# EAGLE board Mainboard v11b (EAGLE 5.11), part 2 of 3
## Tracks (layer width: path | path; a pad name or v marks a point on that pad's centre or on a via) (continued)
KICK_ERR  (via drill 0.3) (continued)
  Bottom 0.203: v30.46,59.39 30.46,61.3 28.55,63.2 19.98,63.2 18.08,65.11 18.08,67.65 v14.58,71.14
KICK_NSS  (via drill 0.3)
  Top 0.203: v29.19,58.76 34.9,58.76 35.86,57.81 36.17,57.49 40.46,57.49 40.72,57.75 IC15.11 | Q2.1 25.06,63.38 v25.06,61.3 | E1.1 13.59,64.83 14.27,64.16 v16.17,64.16
  Bottom 0.203: v29.19,58.76 25.7,58.76 25.06,59.39 v25.06,61.3 19.03,61.3 v16.17,64.16
KILL  (via drill 0.3)
  Top 0.203: IC3.2 100.62,107.66 100.31,107.97 | 100.31,107.97 100.31,109.24 100.62,109.56 R10.1 | 99.67,107.97 100.31,107.97 | v60.78,68.44 61.41,68.44 66.81,68.44 v68.88,70.51 | IC15.27 43.03,49.75 45.38,52.09 v45.38,53.05 | 99.67,107.97 99.67,108.19 R13.1 | v99.04,106.38 99.67,107.02 99.67,107.97
  Bottom 0.203: v99.04,106.38 98.88,106.23 95.39,106.23 93.8,104.64 75.7,104.64 73.48,102.42 73.48,92.73 69.99,89.24 69.99,85.11 63.95,79.08 63.95,76.22 68.88,71.3 v68.88,70.51 | v60.78,68.44 59.67,68.44 59.51,68.28 59.51,66.7 56.49,63.68 56.49,60.66 50.62,54.79 49.98,54.79 48.55,53.36 47.92,53.36 47.6,53.05 v45.38,53.05
LCD_ON
  Top 0.203: IC15.87 65.7,52.25 67.92,50.03 67.92,46.7 69.86,44.75 E14.2
LCD_RESET
  Top 0.203: IC15.88 63.01,52.73 66.02,52.73 68.4,50.35 68.4,46.85 70.26,44.99 E14.4
LED1  (via drill 0.3)
  Top 0.203: IC15.13 42.57,56.75 43,57.17 v43,57.81 | v27.6,118.13 27.6,118.94 Q8.1
  Bottom 0.203: v43,57.81 43.95,57.81 44.27,58.12 45.06,58.92 45.06,60.51 42.84,62.73 42.84,68.28 44.43,69.87 44.43,76.86 43.48,77.81 43.48,91.46 38.87,96.07 38.87,100.83 36.81,102.89 36.81,111.78 35.38,113.21 32.52,113.21 v27.6,118.13
LED2  (via drill 0.3)
  Top 0.203: IC15.9 42.85,58.75 v43,58.6 | v18.39,123.53 18.39,124 Q9.1
  Bottom 0.203: v43,58.6 44.11,58.6 44.59,59.08 44.59,60.35 42.36,62.57 42.36,68.44 43.95,70.03 43.95,76.7 43,77.65 43,91.3 38.39,95.91 38.39,100.67 36.33,102.73 36.33,111.62 35.22,112.73 32.36,112.73 28.23,116.86 22.84,116.86 18.39,121.31 v18.39,123.53
LED3  (via drill 0.3)
  Top 0.203: IC15.132 49.62,65.48 49.19,65.9 48.55,65.9 48.08,66.38 48.08,67.97 48.4,68.28 v50.46,68.28 | v58.4,72.41 58.56,72.25 59.51,72.25 61.89,74.64 61.89,75.11 62.37,75.59 62.37,80.67 64.59,82.89 64.59,84.64 v66.34,86.38 | v78.4,115.91 78.4,116.38 Q11.1
  Bottom 0.203: v78.4,115.91 78.4,107.66 76.34,105.59 75.38,105.59 72.53,102.73 72.53,93.05 66.49,87.02 66.34,86.86 v66.34,86.38 | v50.46,68.28 52.68,68.28 56.81,72.41 v58.4,72.41
LED4  (via drill 0.3)
  Top 0.203: v53,54.63 53,49.87 | IC15.55 52.62,44.41 53,44.79 53,49.87 | 53,49.87 | v88.56,120.35 89.34,120.35 Q10.1 | v66.65,84.8 65.54,83.68 65.54,82.57 63.32,80.35 63.32,75.27 62.84,74.79 v62.84,72.41
  Bottom 0.203: v53,54.63 53.32,54.95 55.86,54.95 59.51,58.6 59.51,63.52 61.26,65.27 61.73,65.75 62.52,66.54 62.84,66.86 v62.84,72.41 | v88.56,120.35 87.29,120.35 79.03,112.1 79.03,107.66 76.5,105.11 75.54,105.11 73,102.58 73,92.89 66.97,86.86 66.97,85.11 v66.65,84.8
M1-BIN+
  Top 0.203: R1.2 91.32,110.56 Q1.5 | IC2.1 90.82,108.65
  Top 0.305: R1.2 91.27,109.09 90.82,108.65
  pour Top (no thermals): 90.78,109.88 90.15,110.51 90.15,116.55 92.37,116.55 92.37,110.51 91.73,109.88
M1-COM  (via drill 0.3)
  Top 0.203: IC17.22 73.48,75.42 73.8,75.11 78.24,75.11 82.36,79.23 R38.2 | IC17.38 73.98,86.57 74.27,86.86 v76.65,86.86 | IC16.3 79.99,88.29 v79.67,87.97
  Bottom 0.203: v76.65,86.86 77.77,87.97 v79.67,87.97
  pour Top (no thermals): 80.62,94.32 83.48,94.32 83.8,94 83.8,79.4 83.48,79.08 82.53,79.08 82.21,79.4 82.21,79.72 82.53,80.03 82.53,81.94 82.21,82.25 80.62,82.25 80.31,82.57 80.62,82.89 82.21,82.89 82.53,83.21 82.53,87.65 82.21,87.97 80.62,87.97 80.31,88.29 80.62,88.61 82.21,88.61 82.53,88.92 82.53,93.37 82.21,93.69 80.62,93.69 80.31,94
M1-HO1
  Top 0.203: IC17.32 77.09,82.05 78.24,83.21 78.24,87.34 80.46,89.56 IC16.2
M1-HO2  (via drill 0.3)
  Top 0.203: IC17.29 77.72,80.55 v77.77,80.51 | IC18.2 80.46,95.27 79.51,94.32 79.51,93.84 v79.03,93.37
  Bottom 0.203: v77.77,80.51 74.75,83.53 74.75,86.54 78.4,90.19 78.4,92.73 v79.03,93.37
M1-HO3
  Top 0.203: IC17.26 77,79.05 77.45,78.6 78.24,78.6 79.03,79.4 79.03,80.83 79.67,81.46 79.67,83.05 80.46,83.84 IC19.2
M1-HO4  (via drill 0.3)
  Top 0.203: IC21.29 29.87,88.09 v29.82,88.13 | IC22.2 27.28,77.81 28.23,78.76 | 28.23,78.76 | 28.23,78.76 28.71,79.24 30.3,79.24 v30.77,79.72
  Bottom 0.203: v29.82,88.13 | v29.82,88.13 32.05,85.91 32.05,83.37 30.77,82.1 v30.77,79.72
M1-HO5
  Top 0.203: IC23.2 27.28,89.24 28.08,90.03 30.14,90.03 30.62,89.56 31.53,89.56 IC21.26
M1-HO6
  Top 0.203: IC20.2 27.28,83.53 27.92,84.16 28.55,84.16 29.35,84.95 29.35,85.43 30.5,86.59 IC21.32
M1-HO7  (via drill 0.3)
  Top 0.203: v29.35,34.95 30.3,34.95 30.5,34.74 IC25.29 | v24.74,26.69 IC26.2
  Bottom 0.203: v29.35,34.95 30.46,34.95 31.41,33.99 31.41,28.6 29.5,26.69 v24.74,26.69
M1-HO8
  Top 0.203: IC25.26 30.91,36.24 30.3,36.85 29.98,36.85 28.71,38.12 IC27.2
M1-HO9  (via drill 0.3)
  Top 0.203: v28.87,33.04 29.07,33.24 IC25.32 | v27.6,32.41 IC24.2
  Bottom 0.203: v28.87,33.04 28.23,33.04 v27.6,32.41
M1-HO10  (via drill 0.3)
  Top 0.203: IC29.29 75.02,29.12 75.07,29.07 v76.5,29.07 | v81.26,38.76 IC30.2
  Bottom 0.203: v76.5,29.07 76.65,29.07 77.13,29.55 77.13,30.19 75.07,32.25 75.07,33.2 80.62,38.76 v81.26,38.76
M1-HO11
  Top 0.203: IC29.26 75.41,27.62 76.18,26.85 78.56,26.85 79.03,27.33 IC31.2
M1-HO12
  Top 0.203: IC29.32 75.5,30.62 77.77,32.88 79.61,32.88 IC28.2
M1-HO13
  Top 0.203: IC34.2 20.35,111.31 24.27,111.31 26.49,109.08 26.49,107.18 26.13,106.82 IC33.29
M1-HO14  (via drill 0.3)
  Top 0.203: IC33.26 24.24,108.32 v23.79,108.77 | v21.57,99.72 IC35.2
  Bottom 0.203: v23.79,108.77 26.65,105.91 26.65,101.94 26.01,101.31 | 26.01,101.31 | 26.01,101.31 24.43,99.72 v21.57,99.72
M1-HO15
  Top 0.203: IC32.2 20.35,105.59 22.84,105.59 23.11,105.32 IC33.32
M1-LO1  (via drill 0.3)
  Top 0.203: IC17.36 76.5,84.05 v76.5,84.8 | v79.03,87.02 IC16.4
  Bottom 0.203: v76.5,84.8 78.72,87.02 v79.03,87.02
M1-LO2
  Top 0.203: IC17.35 77,83.55 77.29,83.84 77.29,88.76 78.08,89.56 78.08,92.1 78.72,92.73 IC18.4
M1-LO3
  Top 0.203: IC17.34 75.07,83.05 74.75,82.73 74.75,78.29 75.38,77.65 79.19,77.65 79.67,78.13 79.67,80.83 80.15,81.3 IC19.4
M1-LO4
  Top 0.203: IC21.35 30.59,85.09 30.3,84.8 30.3,81.46 29.19,80.35 IC22.4
M1-LO5  (via drill 0.3)
  Top 0.203: IC21.34 32.52,85.59 32.84,85.27 32.84,84.32 32.36,83.84 v32.36,82.25 | v28.23,91.78 IC23.4
  Bottom 0.203: v32.36,82.25 33,82.89 33,89.24 30.46,91.78 v28.23,91.78
M1-LO6  (via drill 0.3)
  Top 0.203: IC21.36 30.93,84.59 v30.93,83.84 | IC20.4 27.28,86.06 28.23,85.11 v28.23,84.8
  Bottom 0.203: v30.93,83.84 29.98,84.8 v28.23,84.8
M1-LO7
  Top 0.203: IC26.4 26.96,29.23 27.44,28.76 29.03,28.76 30.46,30.19 32.36,30.19 33.16,30.98 33.16,31.45 32.87,31.74 IC25.35
M1-LO8  (via drill 0.3)
  Top 0.203: v30.14,31.77 30.46,31.77 30.93,32.24 IC25.34 | v30.77,38.12 28.23,40.66 IC27.4
  Bottom 0.203: v30.14,31.77 30.14,33.36 28.71,34.79 28.71,35.11 30.77,37.17 v30.77,38.12
M1-LO9  (via drill 0.3)
  Top 0.203: v30.14,30.82 30.57,31.24 IC25.36 | IC24.4 26.96,34.95 27.6,34.31 v28.23,34.31
  Bottom 0.203: v28.23,34.31 28.55,34.31 29.5,33.36 29.5,31.45 v30.14,30.82
M1-LO10
  Top 0.203: IC29.35 75.73,32.12 76.34,32.73 76.34,35.74 76.97,36.38 79.61,36.38 IC30.4
M1-LO11  (via drill 0.3)
  Top 0.203: IC29.34 73.47,31.62 73.16,31.93 73.16,32.88 73.8,33.52 v73.8,34.15 | v77.13,24.79 IC31.4
  Bottom 0.203: v73.8,34.15 73.64,33.99 73.64,28.28 76.81,24.79 v77.13,24.79
M1-LO12  (via drill 0.3)
  Top 0.203: 79.83,30.6 IC28.4 79.03,30.5 78.72,30.82 v78.4,30.82 | IC29.36 75.28,32.62 v75.7,33.04
  Bottom 0.203: v78.4,30.82 77.92,30.82 v75.7,33.04
M1-LO13  (via drill 0.3)
  Top 0.203: IC33.35 26.2,103.82 26.49,103.53 26.49,103.05 26.01,102.58 v25.54,102.58 | v21.57,113.69 IC34.4
  Bottom 0.203: v25.54,102.58 24.58,103.53 24.58,106.38 22.2,108.77 22.2,113.05 v21.57,113.69
M1-LO14
  Top 0.203: IC33.34 24.1,104.32 23.63,103.84 23.63,102.73 23,102.1 20.35,102.1 IC35.4
M1-LO15  (via drill 0.3)
  Top 0.203: IC33.36 24.74,103.32 v24.74,102.58 | v21.89,106.7 21.89,107.02 20.93,107.97 IC32.4
  Bottom 0.203: v24.74,102.58 24.11,103.21 24.11,106.23 23.63,106.7 v21.89,106.7
M1-VB1
  Top 0.203: IC17.33 76.95,82.55 77.77,83.37 77.77,88.39 C61.1
M1-VB2  (via drill 0.3)
  Top 0.203: IC17.30 77.52,81.05 v77.77,81.3 | v78.72,94.32 78.72,95.06 C62.1
  Bottom 0.203: v77.77,81.3 75.22,83.84 75.22,86.38 79.03,90.19 79.03,92.41 79.67,93.05 79.67,93.69 79.03,94.32 v78.72,94.32
M1-VB3
  Top 0.203: IC17.27 77.13,79.55 77.61,79.08 77.92,79.08 78.56,79.72 78.56,80.98 79.19,81.62 79.19,83.79 C65.1
M1-VB4
  Top 0.203: IC21.33 30.64,86.09 29.82,85.27 29.82,84.48 29.5,84.16 28.55,83.21 C70.1
M1-VB5  (via drill 0.3)
  Top 0.203: IC21.30 30.07,87.59 v29.82,87.34 | C71.1 29.45,78.44 v29.82,78.44
  Bottom 0.203: v29.82,87.34 31.57,85.59 31.57,83.53 29.82,81.78 v29.82,78.44
M1-VB6
  Top 0.203: IC21.27 30.45,89.09 29.98,89.56 28.97,89.56 C74.1
M1-VB7
  Top 0.203: 30.14,32.73 30.16,32.74 | 30.14,32.73 29.5,32.09 29.5,30.92 C79.1 | IC25.33 31.85,32.73 30.14,32.73
M1-VB8  (via drill 0.3)
  Top 0.203: v30.14,34.31 30.62,34.31 30.68,34.24 IC25.30 | v29.19,27.33 28.34,27.33 C80.1
  Bottom 0.203: v30.14,34.31 30.77,33.68 30.77,28.91 v29.19,27.33
M1-VB9
  Top 0.203: C83.1 28.77,35.9 29.35,35.9 29.66,36.22 30.3,36.22 30.77,35.74 IC25.27
M1-VB10
  Top 0.203: IC29.33 75.36,31.12 76.81,32.57 76.81,34.53 C88.1
M1-VB11  (via drill 0.3)
  Top 0.203: IC29.30 76.27,29.62 v76.5,29.87 | v76.81,37.8 77.66,37.8 C89.1
  Bottom 0.203: v76.5,29.87 | v76.5,29.87 | v76.5,29.87 74.59,31.77 74.59,33.36 76.81,35.58 v76.81,37.8
M1-VB12
  Top 0.203: IC29.27 75.55,28.12 76.02,27.65 77.45,27.65 77.77,27.96 C92.1
M1-VB13
  Top 0.203: IC33.33 23.49,104.82 23.16,104.48 23.16,103.95 C97.1
M1-VB14
  Top 0.203: IC33.30 24.18,106.32 23.79,106.7 23.16,106.7 22.2,107.66 C98.1
M1-VB15  (via drill 0.3)
  Top 0.203: IC33.27 23.95,107.82 v23.79,107.97 | v24.27,100.51 24,100.25 C101.1
  Bottom 0.203: v23.79,107.97 26.17,105.59 26.17,102.42 v24.27,100.51
M1-W1  (via drill 0.3)
  Top 0.203: IC17.28 77.43,80.05 v77.77,79.72 | v78.08,93.37 78.08,96.12 C62.2
  Top 0.406: C62.2 79.57,96.54 IC18.1
  Bottom 0.203: v77.77,79.72 74.27,83.21 74.27,86.7 77.77,90.19 77.77,93.05 v78.08,93.37
  other vias: 82.53,96.07 82.53,96.86 83.32,96.86 83.32,96.07 88.56,93.53 87.77,91.94 88.56,92.73 88.56,91.94 86.97,91.94 93.48,83.05 92.69,83.05 91.89,83.05 93.48,82.26 93.48,81.46 94.12,81.78 94.28,82.57
  pour Top (no thermals): 80.62,96.22 81.89,96.22 82.21,95.91 83.48,95.91 83.48,97.02 82.05,97.02 81.89,96.86 80.62,96.86 80.31,96.54
  pour Bottom (no thermals): 89.51,90.83 89.51,88.92 91.73,86.7 91.73,81.62 92.05,81.3 93.64,81.3 93.64,87.02 91.1,89.56 91.1,91.46 88.88,93.69 86.97,93.69 83.64,97.02 82.21,97.02 82.21,95.59 86.02,91.78 88.56,91.78
  pour Top (no thermals): 90.47,82.25 91.42,83.21 93.32,83.21 93.64,82.89 93.64,81.3 90.47,81.3
  pour Top (no thermals): 86.34,94.32 88.24,94.32 88.88,93.69 88.88,92.1 88.56,91.78 86.34,91.78
  pour Bottom (no thermals): 100.94,89.56 97.13,89.56 94.91,87.34 94.91,82.25 93.96,81.3 92.85,82.41 93,82.57 93.64,83.21 93.64,87.97 96.5,90.83 100.94,90.83
  pour Top (no thermals): 91.1,81.46 94.12,81.46 94.91,82.25 94.91,82.89 94.59,83.21 93.64,83.21 93.32,82.89 91.1,82.89
M1-W2  (via drill 0.3)
  Top 0.203: IC17.31 77.22,81.55 78.08,82.41 v78.4,82.41
  Top 0.406: C61.2 79.14,91.46 v80.31,91.46
  Bottom 0.203: 80.31,90.83 80.31,87.02 78.4,85.11 v78.4,82.41
  other vias: 88.56,87.02 88.56,87.81 88.56,86.22 87.77,86.22 86.97,86.22 81.1,91.46 81.89,91.46 91.42,79.56 93,80.35 92.21,80.35 91.42,80.35 90.62,80.35 95.86,81.46 96.5,80.83 95.86,80.19 95.23,80.83
  pour Top (no thermals): 80.15,91.78 80.15,90.51 82.05,90.51 82.05,91.78
  pour Bottom (no thermals): 79.99,91.78 81.89,91.78 85.7,87.97 88.88,87.97 91.1,85.75 91.1,81.3 91.73,80.67 93.32,80.67 93.32,78.76 91.1,78.76 89.51,80.35 89.51,85.11 88.56,86.06 84.43,86.06 79.99,90.51
  pour Top (no thermals): 86.34,88.61 88.24,88.61 88.88,87.97 88.88,86.38 88.56,86.06 86.34,86.06
  pour Top (no thermals): 94.91,79.08 91.42,79.08 90.47,80.03 90.47,80.67 94.91,80.67
  pour Top (no thermals): 96.97,80.83 95.86,81.94 93.32,79.4 93.96,78.76 94.91,78.76
  pour Bottom (no thermals): 100.94,87.65 98.09,87.65 96.81,86.38 96.81,80.67 95.86,79.72 94.75,80.83 94.91,80.98 95.55,81.62 95.55,87.02 97.45,88.92 100.94,88.92
M1-W3  (via drill 0.3)
  Top 0.203: IC17.25 76.86,78.55 77.29,78.13 78.56,78.13 v79.03,78.6
  Top 0.406: C65.2 79.14,85.75 v80.31,85.75
  Bottom 0.203: v79.03,78.6 79.03,83.53 80.31,84.8
  other vias: 81.1,85.75 81.89,85.75 88.56,82.73 88.56,81.94 88.56,81.14 88.56,80.35 87.77,80.35 93.32,77.49 94.28,77.49 94.28,76.54 93.32,76.54
  pour Bottom (no thermals): 100.94,86.86 100.94,85.59 99.04,85.59 98.72,85.27 98.72,79.72 95.23,76.22 93,76.22 93,77.81 94.91,77.81 97.45,80.35 97.45,86.06 98.24,86.86
  pour Top (no thermals): 86.34,80.98 86.97,80.98 89.51,78.44 89.51,76.54 92.37,76.54 92.37,77.49 88.88,80.98 88.88,82.57 88.56,82.89 86.34,82.89
  pour Bottom (no thermals): 79.99,86.06 81.89,86.06 85.07,82.89 88.88,82.89 88.88,80.98 88.88,80.35 88.56,80.03 87.61,80.03 86.66,80.98 83.8,80.98 79.99,84.8
  pour Top (no thermals): 90.78,76.22 90.78,77.81 94.59,77.81 94.59,76.22
  pour Top (no thermals): 80.15,86.06 80.15,84.8 82.05,84.8 82.05,86.06
M1_DIR  (via drill 0.3)
  Top 0.203: IC15.122 54.62,62.6 v54.91,62.25 | E17.7 65.27,73.48 65.7,73.05 65.7,72.09 63.95,70.35 v59.98,70.35
  Bottom 0.203: v54.91,62.25 54.91,64.16 58.08,67.33 58.08,68.92 59.51,70.35 v59.98,70.35
M1_FF1  (via drill 0.3)
  Top 0.203: IC15.92 61.93,54.75 v61.57,55.11 | E17.5 64.86,73.25 65.22,72.89 65.22,72.57 v64.59,71.94
  Bottom 0.203: v61.57,55.11 60.46,56.22 60.46,62.25 61.26,63.05 64.59,63.05 66.34,64.79 66.34,65.75 65.54,66.54 65.54,70.67 64.59,71.62 v64.59,71.94
M1_FF2  (via drill 0.3)
  Top 0.203: IC15.93 62.23,55.25 v61.57,55.9 | E17.3 64.47,72.85 v64.59,72.73
  Bottom 0.203: v61.57,55.9 60.94,56.54 60.94,61.94 61.57,62.57 | 61.57,62.57 | 61.57,62.57 62.21,62.57 64.75,62.57 66.81,64.63 66.81,65.9 66.02,66.7 66.02,70.83 65.7,71.14 65.22,71.62 65.22,72.09 v64.59,72.73
M1_H1  (via drill 0.3)
  Top 0.203: IC17.10 66.17,79.55 65.7,79.08 65.7,78.13 66.97,76.86 v67.45,76.86 | M1.4 93.96,84.8 94.12,84.8 | v101.74,82.57 96.18,82.57 95.55,83.21 95.55,83.68 94.43,84.8 94.12,84.8 | 94.12,84.8 94.12,86.54 95.86,88.29 95.86,90.51 94.91,91.46 v94.12,91.46
  Bottom 0.203: v67.45,76.86 66.81,77.49 66.81,78.13 72.84,84.16 72.84,87.18 76.34,90.67 76.34,94.16 80.62,98.45 87.92,98.45 94.12,92.26 v94.12,91.46 | v101.74,82.57 101.56,82.75 M1B.3
M1_H2  (via drill 0.3)
  Top 0.203: IC17.12 68.24,78.55 v68.24,77.49 | M1.5 91.1,90.19 v91.73,90.83
  Bottom 0.203: v68.24,77.49 68.24,78.29 73.8,83.84 73.8,86.86 77.29,90.35 77.29,93.84 80.94,97.5 86.02,97.5 91.73,91.78 v91.73,90.83 92.37,90.19 94.91,90.19 96.18,91.46 101.26,91.46 102.53,90.19 102.53,85.11 101.16,83.75 M1B.4
M1_H3  (via drill 0.3)
  Top 0.203: M1.6 92.69,89.56 v92.69,90.83 | IC17.11 66.31,79.05 66.18,78.92 66.18,78.29 66.65,77.81 v67.45,77.81
  Bottom 0.203: v67.45,77.81 67.45,78.13 73.32,84 73.32,87.02 76.81,90.51 76.81,94 80.78,97.97 86.5,97.97 92.69,91.78 v92.69,90.83 94.59,90.83 95.86,92.1 101.26,92.1 103.16,90.19 103.16,82.89 102.02,81.75 M1B.2
M1_V5INT  (via drill 0.3)
  Top 0.203: IC17.8 68.44,80.55 68.72,80.83 68.72,82.57 | 68.72,84.32 68.72,83.05 | 69.98,84.32 IC17.46 | 69.98,84.32 68.72,84.32 | IC17.4 67.43,82.57 68.72,82.57 | 68.72,84.32 | 68.72,84.32 68.24,84.8 68.24,85.22 C60.1 | v73.95,71.14 R33.2 R32.2 | 73.48,84.32 69.98,84.32 | v75.86,85.43 74.75,84.32 73.48,84.32 | 73.48,84.32 IC17.39 | 68.72,83.05 IC17.3 | 68.72,83.05 68.72,82.57
  Bottom 0.203: v75.86,85.43 75.86,83.84 77.77,81.94 78.08,81.94 78.4,81.62 78.4,79.4 77.13,78.13 77.13,71.78 76.5,71.14 v73.95,71.14
M1_VREG
  Top 0.203: IC17.40 72.98,86.52 75.44,88.98 C59.1
M2-A  (via drill 0.3)
  Top 0.203: IC21.31 30.37,87.09 29.66,86.38 28.87,86.38 v28.39,85.91
  Top 0.406: C70.2 27.5,81.41 v27.44,81.46
  Bottom 0.203: v28.39,85.91 26.65,84.16 26.65,81.62
  other vias: 18.23,86.22 19.03,86.22 19.03,85.43 26.65,81.46 25.85,81.46 19.03,84.64 18.23,85.43 10.14,89.08 10.77,88.45 10.14,87.81 9.5,88.45
  pour Top (no thermals): 25.7,82.57 25.7,81.3 27.6,81.3 27.6,82.57
  pour Bottom (no thermals): 27.6,81.3 25.7,81.3 22.52,84.48 18.71,84.48 18.08,85.11 18.08,86.38 23.79,86.38 27.6,82.57
  pour Top (no thermals): 21.25,84.48 18.71,84.48 17.12,86.06 17.12,87.97 16.49,88.61 12.04,88.61 11.09,89.56 11.09,90.51 17.12,90.51 19.03,88.61 19.03,87.02 19.66,86.38 21.25,86.38
  pour Top (no thermals): 9.03,88.45 10.14,87.34 12.68,89.88 12.04,90.51 11.09,90.51
  pour Bottom (no thermals): 5.06,81.62 7.91,81.62 9.19,82.89 9.19,88.61 10.14,89.56 11.25,88.45 11.09,88.29 10.45,87.65 10.45,82.25 8.55,80.35 5.06,80.35
M2-B  (via drill 0.3)
  Top 0.203: IC21.28 30.16,88.59 v29.82,88.92 | 26.96,76.54 26.96,76.22
  Top 0.406: C71.2 28.5,76.54 26.96,76.54
  Bottom 0.203: v29.82,88.92 32.52,86.22 32.52,83.21 31.41,82.1 31.41,78.92 28.71,76.22 v25.06,76.22
  other vias: 18.23,79.72 19.03,78.92 18.23,80.51 19.03,80.51 19.03,79.72 25.06,77.02 24.27,77.02 24.27,76.22 12.68,86.86 12.04,86.22 12.04,87.49 11.41,86.86
  pour Top (no thermals): 26.96,76.86 25.7,76.86 25.38,77.17 24.11,77.17 24.11,76.06 25.54,76.06 25.7,76.22 26.96,76.22 27.28,76.54
  pour Bottom (no thermals): 18.08,80.67 18.08,78.76 21.25,78.76 23.95,76.06 25.38,76.06 25.38,77.49 22.2,80.67
  pour Top (no thermals): 16.49,87.65 16.49,86.06 19.03,83.53 19.03,81.3 19.66,80.67 21.25,80.67 21.25,78.76 18.71,78.76 17.12,80.35 17.12,82.89 13.95,86.06 13.63,86.38 13.63,87.65
  pour Top (no thermals): 14.9,87.81 11.88,87.81 11.09,87.02 11.09,86.38 11.41,86.06 12.36,86.06 12.68,86.38 14.9,86.38
  pour Bottom (no thermals): 5.06,79.72 8.87,79.72 11.09,81.94 11.09,87.02 12.04,87.97 13.15,86.86 12.99,86.7 12.36,86.06 12.36,81.3 9.5,78.44 5.06,78.44
M2-C  (via drill 0.3)
  Top 0.203: IC21.25 30.88,90.09 v30.46,90.51
  Top 0.406: C74.2 27.28,87.44 27.26,87.46
  Bottom 0.203: v30.46,90.51 27.44,87.49 26.65,87.34
  other vias: 25.85,87.18 26.65,87.18 27.44,87.18 19.03,91.94 19.03,91.15 19.03,90.35 18.23,91.14 18.23,91.94 12.68,92.73 12.68,91.78 11.73,92.73 11.73,91.78
  pour Top (no thermals): 25.7,88.29 25.7,87.02 27.6,87.02 27.6,88.29
  pour Bottom (no thermals): 27.6,87.02 25.7,87.02 22.52,90.19 18.08,90.19 18.08,92.1 23.79,92.1 27.6,88.29
  pour Top (no thermals): 21.25,90.19 18.08,90.19 17.12,91.14 14.58,91.14 13.63,92.1 13.63,93.05 18.08,93.05 19.03,92.1 21.25,92.1
  pour Top (no thermals): 15.22,93.05 15.22,91.46 11.41,91.46 11.41,93.05
  pour Bottom (no thermals): 5.06,82.41 5.06,83.68 6.96,83.68 7.28,84 7.28,89.56 10.77,93.05 12.99,93.05 12.99,91.46 11.09,91.46 8.55,88.92 8.55,83.21 7.76,82.41
M2-COM
  Top 0.203: IC21.22 34.11,92.58 33.79,92.89 29.03,92.89 28.23,93.69 24.89,93.69 R44.2 | IC21.38 33.61,81.91 33.31,81.62 31.41,81.62 29.5,79.72 27.92,79.72 27.28,79.08 IC22.3
  pour Top (no thermals): 26.96,78.76 24.11,78.76 23.79,79.08 23.79,93.69 24.11,94 25.06,94 25.38,93.69 25.38,93.37 25.06,93.05 25.06,91.14 25.38,90.83 26.96,90.83 27.28,90.51 26.96,90.19 25.38,90.19 25.06,89.88 25.06,85.43 25.38,85.11 26.96,85.11 27.28,84.8 26.96,84.48 25.38,84.48 25.06,84.16 25.06,79.72 25.38,79.4 26.96,79.4 27.28,79.08
M2_DIR  (via drill 0.3)
  Top 0.203: E19.7 41.77,75.47 41.41,75.11 v41.41,74.79 | IC15.8 40.95,59.25 40.46,58.76 v39.66,58.76
  Bottom 0.203: v41.41,74.79 41.41,74.48 40.46,73.52 40.46,61.46 39.66,60.66 v39.66,58.76
M2_FF1  (via drill 0.3)
  Top 0.203: IC15.3 40.8,61.75 40.78,61.78 v39.82,61.78 | E19.5 41.37,75.7 v40.62,74.95 | v40.62,74.95
  Bottom 0.203: v40.62,74.95 39.82,74.16 v39.82,61.78
M2_FF2  (via drill 0.3)
  Top 0.203: IC15.2 40.78,62.25 40.62,62.41 39.66,62.41 v39.03,61.78 | E19.3 40.97,75.94 40.78,75.75 v40.14,75.75
  Bottom 0.203: 39.19,61.94 v39.03,61.78 39.35,62.09 39.35,74.48 40.14,75.27 v40.14,75.75
M2_H1  (via drill 0.3)
  Top 0.203: IC21.10 39.19,89.09 38.87,89.4 38.87,90.35 v39.51,90.99 | v14.58,83.84 13.63,84.8 M2.4 11.25,84.8 10.14,85.91 9.66,86.38 9.34,86.7 4.74,86.7 v4.58,86.54
  Bottom 0.203: v39.51,90.99 | v39.51,90.99 39.51,88.45 32.05,80.98 32.05,78.92 28.71,75.59 17.44,75.59 16.17,76.86 16.17,82.25 v14.58,83.84 | v4.58,86.54 5.82,86.54 M2B.3
M2_H2  (via drill 0.3)
  Top 0.203: v15.53,80.98 15.53,81.62 M2.5 | IC21.12 40.3,90.09 v40.3,90.99
  Bottom 0.203: 15.53,80.35 v15.53,80.98 | v40.3,90.99 40.3,88.61 32.52,80.83 32.52,78.76 28.87,75.11 16.96,75.11 15.53,76.54 15.53,80.35 | 15.53,80.35 12.36,80.35 9.82,77.81 4.74,77.81 3.15,79.4 3.15,84.16 4.52,85.53 M2B.4
M2_H3  (via drill 0.3)
  Top 0.203: v14.58,79.72 M2.6 | IC21.11 41.12,89.59 41.41,89.88 41.41,90.67 v41.09,90.99
  Bottom 0.203: v41.09,90.99 41.09,88.76 33,80.67 33,78.6 29.03,74.64 16.8,74.64 14.58,76.86 | 14.58,76.86 4.74,76.86 2.52,79.08 2.52,85.75 4.3,87.53 M2B.2 | 14.58,76.86 v14.58,79.72
M2_V5  (via drill 0.3)
  Top 0.203: IC21.39 34.11,84 34.27,84.16 37.6,84.16 | 39.03,84.16 37.6,84.16 | 39.03,86.06 39.03,87.97 39.14,88.09 IC21.8 41.14,88.09 v41.57,87.65 | 39.03,85.61 39.03,84.16 | IC21.4 40.13,86.06 39.03,86.06 | IC21.46 37.6,84.16 | 39.03,84.16 39.66,83.53 C69.1 39.91,83.04 | v34.59,96.86 R39.2 R40.2 | IC21.3 40.13,85.61 39.03,85.61 | 39.03,86.06 39.03,85.61
  Bottom 0.203: v34.59,96.86 39.66,91.78 41.25,91.78 41.89,91.14 41.89,87.97 v41.57,87.65
M3-A  (via drill 0.3)
  Top 0.203: C79.2 28.23,33.36 28.62,33.74 IC25.31
  Top 0.406: C79.2 28.02,31.14 26.96,31.14 v26.96,30.5
  other vias: 26.17,30.5 25.38,30.5 18.71,34.31 18.71,35.11 18.71,33.52 17.92,35.11 17.92,34.31 13.79,41.14 14.58,41.14 14.58,41.93 15.38,41.14 15.38,41.93 9.5,40.82 10.14,41.46 10.14,40.19 10.77,40.82
  pour Top (no thermals): 25.22,31.45 25.22,30.19 27.12,30.19 27.12,31.45
  pour Bottom (no thermals): 27.28,30.19 25.38,30.19 22.2,33.36 17.76,33.36 17.76,36.85 13.31,41.3 13.31,41.93 13.63,42.25 15.53,42.25 15.85,41.93 15.85,41.3 19.66,37.49 19.66,36.22 20.62,35.27 23.47,35.27 27.28,31.45
  pour Top (no thermals): 11.09,42.89 14.9,42.89 15.53,42.25 15.53,40.98 11.73,40.98 11.09,41.62
  pour Top (no thermals): 20.62,35.27 17.76,35.27 17.76,33.68 18.08,33.36 20.62,33.36
  pour Top (no thermals): 9.03,40.82 10.14,39.71 12.68,42.25 12.04,42.89 11.09,42.89
  pour Bottom (no thermals): 5.06,33.99 7.91,33.99 9.19,35.27 9.19,40.98 10.14,41.93 11.25,40.82 11.09,40.66 10.45,40.03 10.45,34.63 8.55,32.73 5.06,32.73
M3-B  (via drill 0.3)
  Top 0.203: v30.14,35.58 30.3,35.58 30.64,35.24 IC25.28 | v29.19,26.06 28.66,26.06 C80.2
  Top 0.406: IC26.1 28.13,25.42 C80.2
  Bottom 0.203: v30.14,35.58 30.77,35.58 32.05,34.31 32.05,28.6 29.5,26.06 v29.19,26.06
  other vias: 24.74,25.1 24.74,25.9 23.95,25.1 23.95,25.9 18.71,28.6 18.71,29.39 18.71,27.8 13.31,38.76 14.11,38.76 14.9,38.76 14.9,37.96 15.69,37.96 17.92,28.6 17.92,29.39 12.04,39.87 11.41,39.23 12.68,39.23 12.04,38.6
  pour Top (no thermals): 26.65,25.74 25.38,25.74 25.06,26.06 23.79,26.06 23.79,24.95 25.22,24.95 25.38,25.1 26.65,25.1 26.96,25.42
  pour Bottom (no thermals): 18.71,29.55 17.12,31.14 17.12,36.85 14.9,39.08 12.99,39.08 12.99,38.12 15.53,35.58 15.53,30.5 18.39,27.65 20.93,27.65 23.63,24.95 25.06,24.95 25.06,26.38 21.89,29.55
  pour Top (no thermals): 16.17,40.34 16.17,38.12 15.85,37.8 14.58,37.8 14.27,38.12 13.31,38.12 12.99,38.44 12.99,40.34
  pour Top (no thermals): 20.62,29.55 17.76,29.55 17.76,27.96 18.08,27.65 20.62,27.65
  pour Bottom (no thermals): 5.06,32.09 8.87,32.09 11.09,34.31 11.09,39.39 12.04,40.34 13.15,39.23 12.99,39.08 12.36,38.44 12.36,33.68 9.5,30.82 5.06,30.82
  pour Top (no thermals): 14.9,40.19 11.88,40.19 11.09,39.39 11.09,38.76 11.41,38.44 12.36,38.44 12.68,38.76 14.9,38.76
M3-C  (via drill 0.3)
  Top 0.203: IC25.25 31.04,36.74 30.3,37.49 v30.14,37.49
  Top 0.406: C83.2 28.02,36.85 IC27.1
  Bottom 0.203: v30.14,37.49 28.23,37.49 v26.96,36.22
  other vias: 25.38,36.22 26.17,36.22 18.71,40.03 18.71,40.82 18.71,39.23 17.92,40.03 17.92,40.82 11.72,45.11 11.72,44.15 12.68,45.11 12.68,44.15
  pour Top (no thermals): 25.22,37.17 25.22,35.9 27.12,35.9 27.12,37.17
  pour Bottom (no thermals): 27.28,35.9 25.38,35.9 22.2,39.08 18.71,39.08 17.76,40.03 17.76,40.98 23.47,40.98 27.28,37.17
  pour Top (no thermals): 20.62,39.08 17.44,39.08 17.12,39.39 17.12,40.66 16.17,41.62 16.17,42.89 13.95,45.11 16.17,45.11 17.76,43.52 17.76,41.93 18.71,40.98 20.62,40.98
  pour Top (no thermals): 15.22,45.42 15.22,43.84 11.41,43.84 11.41,45.42
  pour Bottom (no thermals): 5.06,34.79 5.06,36.06 6.96,36.06 7.28,36.38 7.28,41.93 10.77,45.42 12.99,45.42 12.99,43.84 11.09,43.84 8.55,41.3 8.55,35.58 7.76,34.79
M3-COM
  Top 0.203: 24.11,42.42 R50.2 24.59,42.25 27.6,42.25 30.3,39.55 34.11,39.55 34.42,39.24 IC25.22 | IC26.3 27.44,27.96 27.6,28.12 33.31,28.12 33.92,28.73 IC25.38
  pour Top (no thermals): 26.65,27.65 23.79,27.65 23.47,27.96 23.47,42.57 23.79,42.89 24.74,42.89 25.06,42.57 25.06,42.25 24.74,41.93 24.74,40.03 25.06,39.71 26.65,39.71 26.96,39.39 26.65,39.08 25.06,39.08 24.74,38.76 24.74,34.31 25.06,33.99 26.65,33.99 26.96,33.68 26.65,33.36 25.06,33.36 24.74,33.04 24.74,28.6 25.06,28.28 26.65,28.28 26.96,27.96
M3_DIR
  Top 0.203: IC15.46 48.12,42.13 47.28,41.3 47.28,39.39 46.05,38.16 E20.3
M3_FF1
  Top 0.203: IC15.45 47.62,42.26 46.81,41.46 46.81,39.55 45.81,38.56 E20.5
M3_FF2
  Top 0.203: IC15.44 47.12,42.4 46.33,41.62 46.33,39.71 45.58,38.96 E20.7
M3_H1  (via drill 0.3)
  Top 0.203: IC25.10 41.73,35.74 42.2,36.22 42.2,37.33 | v13.63,35.9 13.63,37.17 M3.4 11.25,37.17 10.85,37.57 10.77,37.49 4.26,37.49 v3.79,37.96 | 42.2,37.33 | 42.2,37.33 41.41,38.12 v40.78,38.12 | v40.78,38.12
  Bottom 0.203: v40.78,38.12 39.98,38.12 39.66,37.8 39.66,35.58 28.55,24.47 19.34,24.47 14.9,28.91 14.9,34.63 v13.63,35.9 | v3.79,37.96 4.72,38.9 M3B.3
M3_H2  (via drill 0.3)
  Top 0.203: IC25.12 40.3,36.74 v40.3,37.49 | v14.27,33.36 14.27,34.63 M3.5
  Bottom 0.203: v40.3,37.49 40.3,35.58 28.71,23.99 18.87,23.99 14.27,28.6 14.27,31.45 | 14.27,31.45 v14.27,33.36 | 14.27,31.45 11.41,31.45 10.3,30.34 4.58,30.34 3.79,31.14 3.79,37.17 4.52,37.9 M3B.4
M3_H3  (via drill 0.3)
  Top 0.203: v13.31,30.82 13.31,31.61 13.47,32.09 M3.6 | IC25.11 41.44,36.24 41.73,36.53 41.73,37.01 v41.25,37.49
  Bottom 0.203: 13.31,30.19 v13.31,30.82 | 13.31,30.19 13.31,28.6 18.39,23.52 28.87,23.52 41.25,35.9 v41.25,37.49 | 13.31,30.19 11.09,30.19 10.77,29.87 4.1,29.87 3.15,30.82 3.15,39.39 3.66,39.9 M3B.2
M3_V5  (via drill 0.3)
  Top 0.203: IC25.39 34.42,30.66 34.59,30.82 37.92,30.82 | 37.92,30.82 IC25.46 | 39.35,30.82 37.92,30.82 | 39.35,32.73 39.35,32.24 | IC25.4 39.37,32.74 39.35,32.73 | 39.35,34.74 39.35,37.17 39.66,37.49 v39.66,39.08 | 39.35,34.74 IC25.8 | 39.35,34.74 39.35,32.73 | v35.22,44.16 R45.2 R46.2 | 39.35,30.82 39.98,30.19 40.4,30.19 C78.1 | 39.35,32.24 IC25.3 | 39.35,32.24 39.35,30.82
  Bottom 0.203: v39.66,39.08 35.22,43.52 v35.22,44.16
M4-A  (via drill 0.3)
  Top 0.203: IC28.1 79.83,34.31 v79.83,34.95 | IC29.31 75.79,30.12 v77.77,32.09
  Top 0.406: C88.2 78.3,34.31 79.03,34.31 v79.03,34.95
  Bottom 0.203: v79.83,34.95 79.83,33.84 | 79.35,33.68 v77.77,32.09
  other vias: 80.62,34.95 87.29,31.14 87.29,31.93 87.29,30.34 88.08,30.34 88.08,31.14 95.86,31.61 96.5,30.98 95.86,30.34 95.23,30.98
  pour Top (no thermals): 78.88,35.27 78.88,33.99 80.78,33.99 80.78,35.27
  pour Bottom (no thermals): 78.72,35.27 80.62,35.27 83.8,32.09 88.24,32.09 88.24,30.19 82.53,30.19 78.72,33.99
  pour Top (no thermals): 85.07,30.19 86.66,30.19 87.92,28.91 94.91,28.91 94.91,30.5 89.19,30.5 87.61,32.09 85.07,32.09
  pour Top (no thermals): 96.97,30.98 95.86,32.09 93.32,29.55 93.96,28.91 94.91,28.91
  pour Bottom (no thermals): 100.94,37.8 98.09,37.8 96.81,36.53 96.81,30.82 95.86,29.87 94.75,30.98 94.91,31.14 95.55,31.77 95.55,37.17 97.45,39.08 100.94,39.08
M4-B  (via drill 0.3)
  Top 0.203: IC30.1 79.83,40.03 | IC29.28 75.68,28.62 76.02,28.28 v76.5,28.28 | C89.2 77.55,39.71 77.45,39.71 76.18,38.44 v76.18,37.17
  Top 0.406: C89.2 77.87,40.03 IC30.1
  Bottom 0.203: v76.5,28.28 75.86,28.91 75.86,29.87 74.11,31.61 74.11,33.52 76.18,35.58 v76.18,37.17
  other vias: 81.26,39.55 81.26,40.34 82.05,40.34 82.05,39.55 87.29,36.85 87.29,37.65 87.29,36.06 88.08,36.06 88.08,36.85 93.96,31.93 93.96,33.04 93.32,32.57 94.59,32.57
  pour Top (no thermals): 79.35,39.71 80.62,39.71 80.94,39.39 82.21,39.39 82.21,40.5 80.78,40.5 80.62,40.34 79.35,40.34 79.03,40.03
  pour Bottom (no thermals): 88.24,35.9 88.24,37.8 85.07,37.8 82.37,40.5 80.94,40.5 80.94,39.08 84.11,35.9
  pour Top (no thermals): 85.07,35.9 86.66,35.9 88.56,33.99 89.51,33.04 89.51,31.77 92.37,31.77 92.37,32.73 91.1,33.99 87.92,37.17 87.92,37.8 85.07,37.8
  pour Bottom (no thermals): 100.94,39.71 97.13,39.71 94.91,37.49 94.91,32.41 93.96,31.45 92.85,32.57 93,32.73 93.64,33.36 93.64,38.12 96.5,40.98 100.94,40.98
  pour Top (no thermals): 91.1,31.61 94.12,31.61 94.91,32.41 94.91,33.04 94.59,33.36 93.64,33.36 93.32,33.04 91.1,33.04
M4-C  (via drill 0.3)
  Top 0.203: IC31.1 79.83,28.6 v79.83,29.23 | IC29.25 75.12,27.12 75.86,26.38 77.13,26.38 v77.45,26.06
  Top 0.406: C92.2 78.3,29.23 v79.03,29.23
  Bottom 0.203: v77.45,26.06 79.83,28.44 v79.83,29.23
  other vias: 80.62,29.23 87.29,25.42 87.29,26.22 87.29,24.63 88.08,25.42 88.08,26.22 94.28,27.64 94.28,26.69 93.32,26.69 93.32,27.64
  pour Top (no thermals): 78.88,29.55 78.88,28.28 80.78,28.28 80.78,29.55
  pour Bottom (no thermals): 78.72,29.55 80.62,29.55 83.8,26.38 88.24,26.38 88.24,24.47 82.53,24.47 78.72,28.28
  pour Top (no thermals): 85.07,26.38 87.29,26.38 88.56,27.65 92.37,27.65 92.37,26.38 89.83,26.38 87.92,24.47 85.07,24.47
  pour Top (no thermals): 90.78,26.38 90.78,27.96 94.59,27.96 94.59,26.38
  pour Bottom (no thermals): 100.94,37.01 100.94,35.74 99.04,35.74 98.72,35.42 98.72,29.87 95.23,26.38 93,26.38 93,27.96 94.91,27.96 97.45,30.5 97.45,36.22 98.24,37.01
M4-COM
  Top 0.203: IC29.22 71.89,24.31 72.21,23.99 78.24,23.99 79.03,23.2 81.41,23.2 R56.2 | IC29.38 72.39,35.13 72.84,35.58 75.54,35.58 76.81,36.85 78.4,36.85 79.03,37.49 IC30.3
  pour Top (no thermals): 79.35,37.8 82.21,37.8 82.53,37.49 82.53,22.88 82.21,22.56 81.26,22.56 80.94,22.88 80.94,23.2 81.26,23.52 81.26,25.42 80.94,25.74 79.35,25.74 79.03,26.06 79.35,26.38 80.94,26.38 81.26,26.69 81.26,31.14 80.94,31.45 79.35,31.45 79.03,31.77 79.35,32.09 80.94,32.09 81.26,32.41 81.26,36.85 80.94,37.17 79.35,37.17 79.03,37.49
M4_DIR
  Top 0.203: IC15.80 64.6,48.75 68.4,44.95 68.4,42.25 67.97,41.82 E21.1
M4_FF1  (via drill 0.3)
  Top 0.203: IC15.73 62.07,45.25 v61.73,44.95 | v66.02,44.95 66.02,44.16 65.54,43.68 65.54,43.04 65.97,42.61 E21.11
  Bottom 0.203: v66.02,44.95 v61.73,44.95
M4_FF2  (via drill 0.3)
  Top 0.203: IC15.74 63.79,45.75 63.95,45.58 63.95,44.95 v63.32,44.31 | v66.18,43.36 66.18,43.04 66.37,42.85 E21.9
  Bottom 0.203: v63.32,44.31 65.22,44.31 v66.18,43.36
M4_H1  (via drill 0.3)
  Top 0.203: IC29.10 64.59,28.12 v64.27,27.8 | v92.37,35.58 92.37,34.63 M4.4 94.75,34.63 96.34,33.04 v101.58,33.04
  Bottom 0.203: v92.37,35.58 92.37,36.85 86.97,42.25 79.03,42.25 67.92,31.14 64.59,27.8 v64.27,27.8 | M4B.3 101.44,32.9 v101.58,33.04
M4_H2  (via drill 0.3)
  Top 0.203: v89.83,38.12 89.83,37.17 M4.5 92.37,37.17 v92.37,38.12 | v66.02,26.53 66.02,27.12 IC29.12
  Bottom 0.203: v89.83,38.12 88.88,38.12 86.02,40.98 79.03,40.98 66.02,27.96 v66.02,26.53 | v92.37,38.12 95.86,41.62 101.26,41.62 102.53,40.34 102.53,35.58 100.85,33.9 M4B.4
M4_H3  (via drill 0.3)
  Top 0.203: v87.29,40.98 91.1,40.98 92.37,39.71 M4.6 93.96,40.03 v93.96,40.98 | IC29.11 64.88,27.62 64.59,27.33 64.59,26.85 v65.06,26.38
  Bottom 0.203: v93.96,40.98 95.23,42.25 101.58,42.25 103.16,40.66 103.16,33.04 102.02,31.9 M4B.2 | v87.29,40.98 86.66,41.62 79.03,41.62 65.06,27.65 v65.06,26.38
M4_V5
  Top 0.203: 66.97,31.62 66.97,31.14 | 66.97,31.14 66.97,29.23 66.86,29.12 IC29.8 64.86,29.12 63.48,30.5 61.26,30.5 60.41,31.35 R51.2 R52.2 | IC29.39 71.89,33.2 71.73,33.04 68.39,33.04 | 68.39,33.04 IC29.46 | 68.39,33.04 66.97,33.04 | IC29.4 65.84,31.14 66.97,31.14 | C87.1 66.34,33.68 66.97,33.04 | 66.97,31.62 IC29.3 | 66.97,33.04 66.97,31.62
M5-COM
  Top 0.203: IC33.22 27.75,111.79 27.44,112.1 23.47,112.1 22.52,113.05 22.52,114.32 20.93,115.91 18.86,115.91 R62.2 | IC33.38 27.25,100.64 26.96,100.35 25.38,100.35 24.58,101.15 20.35,101.15 IC35.3
  pour Top (no thermals): 20.62,100.67 17.76,100.67 17.44,100.99 17.44,115.59 17.76,115.91 18.71,115.91 19.03,115.59 19.03,115.28 18.71,114.96 18.71,113.05 19.03,112.73 20.62,112.73 20.93,112.42 20.62,112.1 19.03,112.1 18.71,111.78 18.71,107.34 19.03,107.02 20.62,107.02 20.93,106.7 20.62,106.38 19.03,106.38 18.71,106.07 18.71,101.62 19.03,101.31 20.62,101.31 20.93,100.99
M5-W1  (via drill 0.3)
  Top 0.203: IC33.25 24.58,108.82 v24.58,109.4 | M5.1 7.6,115.59
  Top 0.406: C101.2 22.73,98.45 IC35.1
  Bottom 0.203: v24.58,109.4 25.06,108.92 27.12,106.86 27.12,101.78 24.58,99.24 24.43,99.08 18.87,99.08 v18.71,98.92
  other vias: 18.71,98.13 17.92,98.92 17.92,98.13 12.68,101.62 12.68,102.42 12.68,100.83 11.88,101.62 11.88,102.42 7.28,114.48 6.64,115.12 6.64,116.07 8.07,114.48 7.28,116.7 8.07,116.7
  pour Top (no thermals): 20.62,98.77 19.34,98.77 19.03,99.08 17.76,99.08 17.76,97.97 19.19,97.97 19.34,98.13 20.62,98.13 20.93,98.45
  pour Bottom (no thermals): 11.73,102.58 11.73,101.31 12.36,100.67 14.9,100.67 17.6,97.97 19.03,97.97 19.03,99.4 15.53,102.89 13.95,102.89 6.33,110.51 6.33,112.42 8.55,114.64 8.55,116.86 6.96,116.86 4.74,114.64 4.74,109.56
  pour Top (no thermals): 14.9,102.58 11.73,102.58 11.73,101.62 12.68,100.67 14.9,100.67
  pour Top (no thermals): 8.55,116.86 6.96,116.86 6.33,116.23 6.33,114.96 6.96,114.32 8.55,114.32
M5-W2  (via drill 0.3)
  Top 0.203: IC33.31 23.72,105.82 v23.47,106.07
  Top 0.406: C97.2 21.67,104.16 IC32.1
  Bottom 0.203: v23.47,106.07 22.52,106.07 20.93,104.48
  other vias: 20.3,103.53 21.09,103.53 19.5,103.53 13.47,108.77 14.26,108.77 11.88,108.77 12.68,107.97 12.68,108.77
  pour Top (no thermals): 19.34,104.48 19.34,103.21 21.25,103.21 21.25,104.48
  pour Bottom (no thermals): 21.25,103.21 19.34,103.21 15.22,107.34 12.68,107.34 11.73,108.29 11.73,108.92 16.8,108.92 21.25,104.48
  pour Top (no thermals): 14.58,108.92 12.99,108.92 12.68,109.24 12.68,111.47 10.45,113.69 5.06,113.69 5.06,112.42 10.14,112.42 11.09,111.47 11.09,108.92 13.63,106.38 14.58,106.38
M5-W3  (via drill 0.3)
  Top 0.203: IC33.28 23.49,107.32 23.16,107.66 23.16,109.46 C98.2
  Top 0.406: C98.2 21.67,109.88 IC34.1
  other vias: 20.3,109.24 21.09,109.24 19.5,109.24 10.14,111.46 9.19,111.47 12.68,113.05 8.39,111.47 12.68,112.26 7.44,111.47 12.68,113.85 11.88,113.85 11.88,113.05
  pour Top (no thermals): 19.34,110.19 19.34,108.92 21.25,108.92 21.25,110.19
  pour Bottom (no thermals): 21.25,108.92 19.34,108.92 16.17,112.1 12.36,112.1 10.77,110.51 6.96,110.51 6.96,112.1 9.82,112.1 11.73,114 17.44,114 21.25,110.19
  pour Top (no thermals): 6.96,111.78 10.14,111.78 10.45,111.47 10.45,110.19 10.45,109.88 6.96,109.88
  pour Top (no thermals): 14.9,114 11.73,114 11.73,113.05 12.68,112.1 14.9,112.1
M5_DIR  (via drill 0.3)
  Top 0.203: IC15.124 53.62,63.19 52.21,61.78 51.57,61.78 | E22.5 42.41,97.77 44.11,96.07 v44.11,94.32 | 51.57,61.78 | 51.57,61.78 50.62,62.73 49.67,62.73 49.03,63.36 v48.71,63.36
  Bottom 0.203: v44.11,94.32 44.9,93.53 44.9,82.25 47.76,79.4 47.76,67.33 48.71,66.38 v48.71,63.36
M5_DIRO  (via drill 0.3)
  Top 0.203: IC15.14 42.71,56.25 v43.63,57.17 | v44.11,78.13 44.11,79.08 44.43,79.4 44.43,89.88 41.25,93.05 41.25,95.75 40.14,96.86 38.87,96.86 38.51,97.22 E23.3
  Bottom 0.203: v43.63,57.17 43.95,57.17 45.54,58.76 45.54,60.66 43.32,62.89 43.32,68.13 44.9,69.71 44.9,77.02 44.11,77.81 v44.11,78.13
M5_FF1  (via drill 0.3)
  Top 0.203: E22.1 41.61,97.3 42.68,96.22 42.68,93.53 45.86,90.35 45.86,79.24 46.02,79.08 v46.02,78.76 | IC15.19 42.91,53.75 v43.79,54.63
  Bottom 0.203: v43.79,54.63 46.97,57.81 46.97,61.14 45.54,62.57 45.54,68.44 46.33,69.24 46.33,77.49 46.02,77.81 v46.02,78.76
M5_FF2  (via drill 0.3)
  Top 0.203: E23.7 39.31,98.01 39.51,97.81 40.46,97.81 41.41,96.86 | 41.41,96.86 | 41.41,96.86 42.2,96.07 42.2,93.37 45.38,90.19 v45.38,78.13 | IC15.18 42.61,54.25 v43,54.63
  Bottom 0.203: v43,54.63 46.49,58.28 46.49,60.98 44.27,63.2 44.27,67.81 45.86,69.4 45.86,77.33 45.38,77.81 v45.38,78.13
M5_H1  (via drill 0.3)
  Top 0.203: IC33.10 35.06,107.82 v35.22,107.97 35.3,108.05 RN4.4 | M5.6 6.33,99.72 6.96,99.08 11.41,99.08 12.99,97.5 15.85,97.5 18.39,94.95 v18.39,94.64
  Bottom 0.203: v35.22,107.97 35.22,107.81 28.55,101.15 | 28.55,101.15 | 28.55,101.15 22.04,94.64 v18.39,94.64
M5_H2  (via drill 0.3)
  Top 0.203: v11.09,100.35 M5.7 | IC33.11 34.77,108.32 35.06,108.61 | 35.06,108.61 35.06,109.08 v34.59,109.56 | RN4.3 35.13,108.67 35.06,108.61
  Bottom 0.203: v11.09,100.35 13.95,97.5 19.03,97.5 20.14,98.61 24.58,98.61 33.95,107.97 33.95,108.92 v34.59,109.56
M5_H3  (via drill 0.3)
  Top 0.203: v8.55,97.81 M5.8 | IC33.12 33.8,110.05 v33.95,110.19 34.74,110.19 35.14,109.8 RN4.1
  Bottom 0.203: v8.55,97.81 10.77,97.81 13.31,95.27 22.04,95.27 34.43,107.66 34.43,108.29 35.22,109.08 35.22,109.72 35.06,109.88 | v33.95,110.19 34.74,110.19 35.06,109.88 | 35.06,109.88
M5_V5  (via drill 0.3)
  Top 0.203: IC33.39 27.75,102.73 28.08,103.05 31.25,103.05 | 32.52,104.82 IC33.4 | 32.52,103.05 32.52,104.32 | 31.25,103.05 IC33.46 | 31.25,103.05 32.52,103.05 | 32.52,103.05 33.31,102.26 C96.1 | 32.52,104.82 32.52,106.82 | 32.52,106.82 IC33.8 | 32.52,106.82 32.52,109.08 | 32.52,109.08 | 32.52,109.08 33,109.56 v33,110.51 | v28.87,115.43 28.02,115.43 R57.2 R58.2 | 32.52,104.32 IC33.3 | 32.52,104.32 32.52,104.82
  Bottom 0.203: v33,110.51 33,111.31 v28.87,115.43
MSL_CS
  Top 0.203: E6.1 10.1,46.02 10.45,46.38 15.85,46.38 27.6,58.12 34.59,58.12 35.7,57.01 40.62,57.01 40.85,57.25 IC15.12
MSR_CS  (via drill 0.3)
  Top 0.203: E5.1 98.37,45.11 v99.35,45.11 | IC15.54 52.12,44.54 52.37,44.79 v52.37,50.35
  Bottom 0.203: v52.37,50.35 | v52.37,50.35 52.84,50.82 58.72,50.82 60.94,48.6 66.02,48.6 70.46,44.16 95.86,44.16 96.18,44.47 98.4,44.47 99.04,45.11 v99.35,45.11
N$1
  Top 0.203: IC10.5 82.84,56.79 L10.2
N$3
  Top 0.203: R19.1 IR2.P$2
N$4
  Top 0.406: SD.4 84.84,60.04 C20.1 84.33,60.35 IC10.1
N$5
  Top 0.203: ENC2.2 3.79,82.89 5.06,81.62 5.06,79.08 11.09,73.05 14.9,73.05 20.62,67.33 20.62,60.51 20.81,60.31 E18.8
N$6
  Top 0.406: R16.2 C13.1 33.73,66.48 33.95,66.7 33.95,67 IC4.1
N$7  (via drill 0.3)
  Top 0.305: 94.76,108.61 IC2.12 92.72,108.65 v92.37,108.29 | v89.19,112.1 89.19,110.93 R9.2 87.5,112.42 Q1.4
  Bottom 0.305: v92.37,108.29 89.19,111.47 v89.19,112.1
N$8
  Top 0.203: ENC2.4 3.79,80.35 4.42,79.72 4.42,79.08 11.09,72.41 14.58,72.41 19.98,67.02 19.98,60.35 20.41,59.91 E18.6
N$9
  Top 0.203: ENC3.2 1.88,30.19 0.93,31.14 0.93,48.28 2.2,49.55 11.25,49.55 20.81,59.11 E18.2
N$10
  Top 0.203: 89.46,106.69 IC2.4 | 89.46,106.69 R2.2 | R4.2 88.73,105.97 89.46,106.69
N$11
  Top 0.203: IC2.6 90.82,105.39 91.42,104.8 91.42,104.54 R7.1 R11.2
N$12  (via drill 0.3)
  Top 0.203: IC33.15 31.25,111.47 31.89,112.1 v34.9,112.1 | E23.2 38.11,99.75 37.48,99.75 v37.44,99.72
  Bottom 0.203: v37.44,99.72 37.44,100.99 35.86,102.58 35.86,111.15 v34.9,112.1
N$13
  Top 0.203: ENC3.4 1.72,27.65 0.45,28.91 0.45,48.44 2.2,50.19 11.09,50.19 20.41,59.51 E18.4
N$14
  Top 0.203: ENC1.4 104.44,87.65 105.39,86.7 105.39,82.25 103.16,80.03 100.94,80.03 94.91,74 86.97,74 81.89,68.92 79.67,68.92 74.16,63.41 E16.4
N$15
  Top 0.203: IC11.12 INT.TP
N$16
  Top 0.203: ENC1.2 103.48,85.11 103.48,80.98 103.16,80.67 100.62,80.67 94.59,74.64 86.66,74.64 81.58,69.56 79.35,69.56 73.6,63.8 E16.2
N$17
  Top 0.203: SD.2 83.09,65.04 75.03,56.97 E8.6
N$19
  Top 0.203: IC15.106 63.82,61.75 64.75,60.82 C44.1 64.64,60.77
N$20
  Top 0.203: 72.3,87.94 C64.1 71.98,87.69 IC17.42
N$21
  Top 0.203: SD.5 85.75,57.54 83.96,55.74 76.02,55.74 75.19,56.57 E8.8
N$22
  Top 0.203: 70.78,87.97 C64.2 70.62,87.97 71.48,87.11 IC17.43
N$23
  Top 0.203: SD.7 86.29,52.61 83.8,55.11 78.24,55.11 78.12,55.23 E7.2
N$24
  Top 0.203: SD.8 86.25,50.91 84.91,52.25 84.91,53.2 83.48,54.63 78.08,54.63 77.88,54.83 E7.4
N$25
  Top 0.406: R29.1 18.52,128 LED2.AG
N$26
  Top 0.203: IC11.20 55.51,76.25 55.7,76.06 55.7,74 55.6,74 C23.1
N$27
  Top 0.203: L13.1 49.51,73.63 | L13.1 50.73,73.79 C26.1 C25.1 51.75,74.04 IC11.13 | L13.1 49.61,73.84
N$28
  Top 0.406: SG1.4 81.18,42.33 73.32,50.19 73.32,50.5 71.59,52.24 Q4.3
N$29
  Top 0.203: IC17.18 71.48,74.44 R35.2
N$30
  Top 0.203: IC17.16 70.48,75.03 C63.1 R34.2
N$31
  Top 0.203: IC15.71 60.62,40.45 C43.1
N$32
  Top 0.203: IC17.20 72.48,73.85 R32.1
N$33  (via drill 0.3)
  Top 0.203: IC17.23 73.98,75.88 v74.11,75.75 | v76.5,73.68 75.6,73.68 R36.2 R33.1 | R33.1
  Bottom 0.203: v74.11,75.75 76.18,73.68 v76.5,73.68
N$34  (via drill 0.3)
  Top 0.203: IC29.15 68.39,24.47 68.24,24.31 66.81,24.31 v66.02,25.1 | E21.6 67.17,38.8 66.65,38.28 v66.65,37.8
  Bottom 0.203: v66.02,25.1 64.91,25.1 63.16,26.85 63.16,29.23 66.65,32.73 v66.65,37.8
N$35
  Top 0.203: SD.9 86.82,70.04 74.56,57.77 E8.2
N$36
  Top 0.203: SD.1 84.96,67.54 74.79,57.37 E8.4
N$37
  Top 0.203: SD.CD 86.12,49.61 84.43,51.3 84.43,52.73 83,54.16 77.92,54.16 77.65,54.43 E7.6
N$38
  Top 0.203: IC2.9 97.12,106.69 97.77,107.34 97.77,108.19 R13.2
N$39
  Top 0.203: SD.WP 86.2,48.41 83.96,50.66 83.96,52.57 82.84,53.68 77.77,53.68 77.41,54.03 E7.8
N$40
  Top 0.406: Q9.3 15.38,125.76 R29.2
N$41  (via drill 0.3)
  Top 0.203: IC14.12 46.8,113.63 C32.1 v47.92,113.69 | C31.1 46.17,99.46 | IC14.37 46.8,99.34 C31.1 | v46.33,98.13 46.33,98.87 C31.1 | v55.54,113.05 55.76,112.84 C33.1 55.76,111.63 IC14.64 | IC14.49 55.58,102.64 C30.1 55.86,102.26 55.22,101.62 53.32,101.62 51.09,103.84 51.09,106.38 v50.62,106.86
  Bottom 0.203: v46.33,98.13 46.49,98.28 46.49,102.73 50.14,106.38 | v55.54,113.05 55.54,111.78 51.09,107.34 | v47.92,113.69 47.92,109.56 v50.62,106.86 | 51.09,107.34 | v50.62,106.86 51.09,107.34 | 50.14,106.38 | 50.14,106.38 v50.62,106.86
N$42
  Top 0.203: IC12.3 42.06,121.62 40.09,121.62 C27.1 39.66,121.15 38.71,120.2 38.71,118.77 37.76,117.81 35.86,117.81 35.57,118.1 USB1.1
N$43
  Top 0.203: L4.1 78.52,100.3 L3.2
N$44
  Top 0.203: IC14.7 49.3,112.85 49.83,113.37 49.83,114.32 46.33,117.81 41.89,117.81 41.41,117.34 35.06,117.34 34.92,117.48 USB1.2 34.9,118.79
N$45
  Top 0.406: IR2.P$1 100.38,100.35 99.35,100.35 99.35,101.31 99.29,101.31 L7.2
N$46
  Top 0.203: 61.22,82.86 E9.8 | 61.22,82.86 63.48,85.11 Q5.3 | EXT.2 60.2,82.86 61.22,82.86
N$47
  Top 0.203: IC2.5 89.97,106.05 89.67,105.75 89.67,104.42 | R7.2 89.67,104.42 | R4.1 89.51,104.27 89.67,104.42
N$48
  Top 0.203: C5.1 87.29,110.73 R9.1
N$49
  Top 0.203: IC14.8 48.8,112.98 49.19,113.37 49.19,114.32 46.33,117.18 41.89,117.18 41.57,116.86 34.9,116.86 34.27,117.5 USB1.3
N$50
  Top 0.203: IC25.15 37.92,39.55 38.55,40.19 41.57,40.19 42,39.76 E20.12
N$51
  Top 0.203: IC14.6 49.8,112.61 R26.2
N$52
  Top 0.203: IC14.9 48.3,113.12 48.55,113.37 48.55,114 47.6,114.96 C34.1 46.87,115.69 46.02,116.55 44.74,116.55 44.11,115.91 L15.2
N$53
  Top 0.203: 8.72,95.59 R20.1
  Top 0.406: Q3.3 8.72,95.59
N$54
  Top 0.203: R20.2 7.75,91.78
  Top 0.406: 7.75,91.78 IR1.P$2
N$55  (via drill 0.3)
  Top 0.203: IC14.14 45.8,111.04 v46.02,110.83 | v43.79,112.73 43.69,112.84 R24.1
  Bottom 0.203: v46.02,110.83 44.11,112.73 v43.79,112.73
N$56  (via drill 0.3)
  Top 0.203: IC14.4 50.8,111.28 v51.09,110.99 | L14.2 55.12,115.44 C35.1 56.49,113.59 v56.49,113.37
  Bottom 0.203: v51.09,110.99 52.84,110.99 54.59,112.73 54.59,113.16 55.13,113.7 56.24,113.7 56.49,113.44 v56.49,113.37 56.23,113.69
N$57
  Top 0.203: E5.2 98.37,43.08 98.88,42.57 100.33,42.57 MSR.P$2
N$58
  Top 0.203: IC14.2 51.8,112.66 51.73,112.73 51.73,114.32 51.41,114.64 51.08,114.64 Q6.3
N$59
  Top 0.203: RN2.1 47.73,120.01 R25.1 49.29,118.45 IC13.4
N$60  (via drill 0.3)
  Top 0.203: R25.2 49.72,119.72 IC13.3 v53,119.72 | v57.13,109.88 55.88,108.63 IC14.61
  Bottom 0.203: v53,119.72 57.76,114.96 57.76,110.51 v57.13,109.88
N$61  (via drill 0.3)
  Top 0.203: RN2.3 50.21,121.24 50.46,120.99 IC13.2 v53,120.99 | v54.27,120.99 54.27,118.45 57.76,114.96 57.76,111.47 55.43,109.13 IC14.62
  Bottom 0.203: v54.27,120.99 v53,120.99
N$62
  Top 0.203: IC14.63 55.15,109.63 57.13,111.62 57.13,114.96 53.63,118.45 53.63,121.62 53,122.26 IC13.1 50.46,122.26 50.06,121.87 RN2.4
N$63
  Top 0.203: E5.4 97.97,42.84 99.35,41.46 100.19,41.46 MSR.P$3
N$64
  Top 0.203: IC14.38 47.3,100.02 47.6,99.72 47.6,97.18 48.98,95.8 E15.11
N$65
  Top 0.203: IC17.5 66.29,82.05 64.27,80.03 64.27,78.92 | 64.27,78.92 64.27,77.65 64.47,77.46 E17.4 | 64.27,78.92
N$66
  Top 0.203: IC14.39 47.8,100.15 48.24,99.72 48.24,97.18 49.38,96.03 E15.9
N$67
  Top 0.203: IC17.6 66.43,81.55 64.75,79.87 64.75,77.81 64.86,77.69 E17.6
N$68
  Top 0.203: E5.6 97.57,42.29 99.82,40.04 MSR.P$4
N$69
  Top 0.203: L4.2 79.73,98.77 C16.1 81.39,99.11 IC7.2
N$70
  Top 0.203: E2.8 80.11,101.66 80.89,100.88 IC7.1
N$71
  Top 0.203: E5.8 97.17,41.42 99.8,38.79 MSR.P$5
N$72
  Top 0.203: E2.2 80.27,102.86 80.89,103.48 IC7.10
N$73
  Top 0.203: E2.6 80.74,102.06 81.89,103.21 IC7.8
N$74
  Top 0.203: E2.4 80.5,102.46 81.39,103.34 IC7.9
N$75
  Top 0.203: IC6.1 92.69,99.08 92.37,99.4 92.37,100.35 91.73,100.99 IC6.4 | IC6.4 90.94,100.99 | IC7.4 82.39,100.69 82.53,100.83 89.83,100.83 89.99,100.99 IC6.4
N$76
  Top 0.203: C15.1 L5.2 91.1,98.83 IC6.5
N$77
  Top 0.203: R11.1 95.12,105.39 IC2.7
N$78  (via drill 0.3)
  Top 0.203: IC2.3 90.62,107.34 v92.37,107.34 | IC3.7 104.59,107.66 104.75,107.81 104.75,108.61 104.12,109.24 | 104.12,109.24 103.8,109.56 R10.2 | v104.44,109.24 104.12,109.24
  Bottom 0.203: v92.37,107.34 92.69,107.02 93.96,107.02 96.18,109.24 v104.44,109.24
N$79  (via drill 0.3)
  Top 0.203: IC3.5 103.46,106.36 103.16,106.07 v103.16,104.16 | PWR.2 102.71,20.66 v100.31,20.66
  Bottom 0.203: v103.16,104.16 105.39,101.94 105.39,47.65 106.34,46.7 106.34,46.06 105.39,45.11 105.39,25.74 v100.31,20.66
N$80
  Top 0.203: E9.6 60.82,80.78 60.3,81.3 59.83,81.3 58.87,82.25 58.87,86.7 | 58.87,86.7 57.31,88.26 EXT.3 | 58.87,86.7 61.89,86.7 62.53,87.34 Q5.2
N$81
  Top 0.203: C3.1 104.91,106.01 104.91,106.85 104.75,107.01 | 104.75,107.01 IC3.6 | 104.75,107.01 105.23,107.5 105.23,109.3 R3.1
N$82
  Top 0.203: C7.1 C8.1 | IC3.3 100.62,107.01 98.82,105.22 C8.1 | C8.1 98.88,105.11
N$83
  Top 0.203: E9.4 60.42,80.55 60.14,80.83 59.67,80.83 58.4,82.1 58.4,84.64 54.77,88.26 EXT.5
N$84
  Top 0.203: IC2.10 96.5,107.34 C4.1
N$85
  Top 0.203: E10.8 58.2,80.54 57.13,81.62 55.86,81.62 55.22,82.25 EXT.6
N$86
  Top 0.203: EXT.4 57.31,82.39 59.51,80.19 59.98,80.19 E9.2
N$87
  Top 0.203: E10.2 57,80.47 56.81,80.67 54.27,80.67 52.23,82.71 EXT.8
N$88
  Top 0.203: E10.4 57.4,80.71 56.97,81.14 54.75,81.14 53.63,82.25 53.63,87.02 52.37,88.29 52.37,88.66 EXT.7
N$89  (via drill 0.3)
  Top 0.203: E16.8 73.6,62.61 73.95,62.25 v74.59,62.25 | ENC4.2 104.28,27.65 105.39,28.76 105.39,46.06 v105.7,46.38
  Bottom 0.203: v74.59,62.25 89.19,62.25 105.07,46.38 v105.7,46.38
N$90
  Top 0.203: IC17.14 69.48,76.04 69.19,75.75 68.4,75.75 67.92,76.22 66.81,76.22 66.49,76.54 66.02,76.54 65.66,76.19 E17.10
N$91
  Top 0.203: IC17.9 67.41,80.03 65.7,80.03 65.22,79.56 65.22,78.44 65.22,77.97 65.27,77.93 E17.8
N$92
  Top 0.203: E17.2 64.06,77.22 63.8,77.49 63.8,80.19 65.54,81.94 66.02,82.41 66.02,83.21 66.36,83.55 IC17.2
N$93
  Top 0.203: USB.2 68.24,108.97 68.24,106.54 68.75,106.03 E4.8
N$94  (via drill 0.3)
  Top 0.203: v75.22,61.62 75.22,62.57 74.79,63.01 E16.6 | ENC4.4 104.28,30.19 104.75,30.66 v104.75,32.73
  Bottom 0.203: v75.22,61.62 88.88,61.62 104.75,45.74 v104.75,32.73
N$95
  Top 0.203: DISPLAY.29 64.43,17.48 63.16,18.76 63.16,24.1 L12.1
N$96
  Top 0.406: L6.2 6.33,90.53 IR1.P$1
N$97  (via drill 0.3)
  Top 0.203: DISPLAY.4 31.41,20.02 31.73,19.71 v32.36,19.71 | E13.1 49.54,28.95 45.06,24.47 v45.06,23.52
  Bottom 0.203: v32.36,19.71 34.9,22.25 43.79,22.25 v45.06,23.52
N$98  (via drill 0.3)
  Top 0.203: DISPLAY.2 28.87,19.71 v29.82,19.71 | v49.83,28.28 49.94,28.4 E13.3
  Bottom 0.203: v29.82,19.71 33.63,23.52 43.16,23.52 47.92,28.28 v49.83,28.28
N$99  (via drill 0.3)
  Top 0.203: v33.95,18.44 DISPLAY.5 | v50.46,27.65 50.46,28.6 50.34,28.72 E13.5
  Bottom 0.203: v33.95,18.44 33.95,19.71 35.86,21.61 44.11,21.61 44.74,22.25 46.02,22.25 50.46,26.69 v50.46,27.65
N$100  (via drill 0.3)
  Top 0.203: v71.1,41.93 71.06,41.97 E14.7 | v77.13,18.44 DISPLAY.39
  Bottom 0.203: v77.13,18.44 74.27,21.3 65.54,21.3 60.78,26.06 60.78,34.15 68.56,41.93 v71.1,41.93
N$101
  Top 0.203: 66.02,109.19 USB.3 66.34,108.88 66.34,107.02 68.52,104.83 E4.2
N$102
  Top 0.406: NRF24.2 21.78,9.65 C21.1 21.83,12.14 L11.1
N$103
  Top 0.203: NRF24.8 26.38,5.78 E11.2
N$104  (via drill 0.3)
  Top 0.203: Q2.2 22.2,65.74 v21.89,65.43 | E1.5 14.06,65.63 14.27,65.43 v18.71,65.43
  Bottom 0.203: v21.89,65.43 v18.71,65.43
N$105
  Top 0.203: IC21.15 37.61,92.89 38.08,93.37 40.3,93.37 43.95,89.72 43.95,79.56 42.57,78.17 E19.12
N$106
  Top 0.203: IC17.15 69.98,75.9 69.51,75.43 | 69.51,75.43 | 69.51,75.43 69.35,75.27 68.24,75.27 67.76,75.75 66.06,75.75 E17.12
N$107
  Top 0.203: R6.1 86.34,104.27 85.33,105.27 83.96,105.27 83,106.23 83,108.61 84.42,110.02 IC1.6
N$108
  Top 0.203: IC1.3 85.72,107.54 C1.1 85.6,107.02 85.38,107.02 84.43,106.07 L1.1
N$109
  Top 0.203: IC11.10 50.03,76.75 48.87,75.59 48.87,74.06 C24.1
N$110
  Top 0.406: R28.1 25.54,125.45 LED2.AR
N$111
  Top 0.406: MSR.P$6 97.65,37.54 L8.2
N$112
  Top 0.203: NRF24.7 20.93,2.88 22.52,2.88 25.98,6.34 E11.4
N$113
  Top 0.203: NRF24.6 25.58,7.53 E11.6
N$114
  Top 0.203: NRF24.5 20.93,5.42 22.52,5.42 25.18,8.08 E11.8
N$115
  Top 0.203: NRF24.4 24.78,9.27 E11.10
N$116
  Top 0.203: NRF24.3 20.93,7.96 22.52,7.96 24.38,9.82 E11.12
N$117
  Top 0.203: E6.2 10.1,42.53 7.31,39.74 MSL.P$2
N$118
  Top 0.203: E12.6 57.33,76.02 55.6,77.75 IC11.23
N$119
  Top 0.203: E12.8 57.73,76.26 55.73,78.25 IC11.24
N$120
  Top 0.203: LED1.A R15.1
N$121  (via drill 0.3)
  Top 0.203: IC11.9 50.22,77.25 v50.14,77.33 | E12.2 56.53,75.23 v56.33,75.43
